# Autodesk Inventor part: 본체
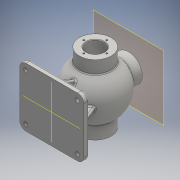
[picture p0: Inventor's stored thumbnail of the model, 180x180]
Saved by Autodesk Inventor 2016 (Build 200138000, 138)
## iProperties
Created: 2017-01
Part Number: 본체
Material: 일반
Document SubType Name: Modeling
Designer: Administrator
Density: 1 g/cm^3
Appearance: 기본값
Author: Administrator
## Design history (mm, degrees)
sketch "스케치1"
  geometry: L1 (0, 0)-(125, 0); L2 (125, 0)-(125, -115); L3 (125, -115)-(0, -115); L4 (0, -115)-(0, 0)
  constraints: 8 end point, 2 parallel, 1 horizontal, 1 perpendicular
  dimensions: "d0" = 115 distance of L1.end L2.end; "d1" = 125 distance of L2.end L3.end
extrude "돌출1" new body sketch "스케치1" distance "d2" = 10; taper "d3" = 0 deg
sketch "스케치2"
  geometry: L1 (-125, 0)-(-125, 115) reference; L2 (-125, 0)-(0, 0) reference; 1 further point
  dimensions: "d4" = 12 distance from line of L1 point (-113, 12); "d5" = 12 distance from line of L2 point (-113, 12)
hole "구멍1" sketch "스케치2" at (-113, 12) diameter "d6" = 8; stored, may be unused: countersink angle "d10" = 90 deg, drill point angle "d12" = 118 deg; dims "d7" = 6, "d8" = 12, "d9" = 3, "d11" = 8
fillet "모깎기1" dims "d19" = 12
node "작업 평면1"
sketch "스케치3"
  geometry: L1 (113.5, 116)-(113.5, 102.5); L2 (113.5, 85)-(-22.5, 85); L3 (-22.5, 102.5)-(-22.5, 116); L4 (91, 0)-(0, 0) reference; L5 (-12, 10)-(-12, 0) reference; L6 (-22.5, 116)-(2.512, 116); L7 (88.488, 116)-(113.5, 116); L8 (-6.5, 102.5)-(6.222, 102.5); L9 (-6.5, 102.5)-(-22.5, 102.5); L10 (113.5, 102.5)-(97.5, 102.5); L11 (97.5, 102.5)-(97.5, 103.5); L12 (97.5, 103.5)-(95.75, 103.5); L13 (95.75, 103.5)-(95.75, 102.5); L14 (95.75, 102.5)-(84.778, 102.5); A1 r 53 centre (45.5, 85) between (88.488, 116) and (2.512, 116); A2 r 43 centre (45.5, 85) between (84.778, 102.5) and (6.222, 102.5); 2 further points
  constraints: 24 end point, 7 perpendicular, 4 point on circle, 3 parallel, 2 centre point, 2 horizontal, 2 point on line, 1 midpoint, 1 vertical
  dimensions: "d22" = 136 distance of L3.end L1.start; "d23" = 85 distance between parallel lines of L4 L2; "d24" = 31 distance of L2.end L3.end; "d25" = 10.5 distance between parallel lines of L5 L3; "d26" = 53 radius of A1; "d28" = 43 radius of A2; "d36" = 17.5 distance between parallel lines of L2 L8; "d39" = 16 distance of L1.end L10.end; "d40" = 18.5 distance between parallel lines of L2 L12; "d41" = 17.5 distance between parallel lines of L2 L14; "d42" = 17.5 distance between parallel lines of L2 L10; "d43" = 1.75 distance of L11.end L12.end; "d44" = 136 distance between parallel lines of L3 L1; "d45" = 31 distance between parallel lines of L2 L6; "d46" = 68 distance of L2.end A1.centre
revolve "회전1" sketch "스케치3" stored, may be unused: angle "d32" = 90 deg
fillet "모깎기2" dims "d47" = 3
chamfer "모따기1" distance "d48" = 1; stored, may be unused: second distance "d49" = 2, angle "d50" = 45 deg
node "작업 평면2"
sketch "스케치4"
  geometry: L1 (-93.5, -125.5)-(-31.5, -125.5) reference; L2 (-125, -103)-(-125, -12) reference; C1 r 27 at (-62.5, -57.5); 1 further point
  constraints: 1 centre point
  dimensions: "d52" = 68 distance from line of C1.centre L1; "d53" = 62.5 distance from line of L2 C1.centre; "d54" = 54 diameter of C1
extrude "돌출2" join sketch "스케치4" stored distance "d55" = 10; taper "d56" = 0 deg
sketch "스케치5"
  geometry: C1 r 13 at (0, 0); 1 further point
  constraints: 1 centre point
  dimensions: "d57" = 26 diameter of C1
extrude "돌출3" cut sketch "스케치5" distance "d58" = 58; taper "d59" = 0 deg
fillet "모깎기3" dims "d60" = 3
chamfer "모따기2" distance "d61" = 1; stored, may be unused: second distance "d62" = 2, angle "d63" = 45 deg
sketch "스케치6" dims "d64" = 40
  geometry: 3 further points
  constraints: 1 horizontal alignment, 2 other
hole "구멍2" sketch "스케치6" at (-20, 0) diameter "d65" = 3.242; stored, may be unused: countersink angle "d69" = 90 deg, drill point angle "d71" = 118 deg; dims "d66" = 9, "d67" = 12, "d68" = 3, "d70" = 11
sketch "스케치7" dims "d75" = 48
  geometry: 3 further points
  constraints: 1 vertical alignment, 2 other
hole "구멍3" sketch "스케치7" at (0, 24) diameter "d76" = 3.242; stored, may be unused: countersink angle "d80" = 90 deg, drill point angle "d82" = 118 deg; dims "d77" = 16, "d78" = 12, "d79" = 3, "d81" = 19
sketch "스케치8" dims "d86" = 45
  geometry: 3 further points
  constraints: 1 vertical alignment, 2 other
hole "구멍4" sketch "스케치8" at (0, 22.5) diameter "d87" = 3.242; stored, may be unused: countersink angle "d91" = 90 deg, drill point angle "d93" = 118 deg; dims "d88" = 12, "d89" = 12, "d90" = 3, "d92" = 15
node "작업 평면3"
sketch "스케치11"
  geometry: L1 (101, 10)-(110, 10) reference; L2 (103, 10)-(86.485, 50.876); L3 (103, 10)-(-2, 10); L4 (101, 10)-(0, 10) reference; L5 (14.515, 50.876)-(-2, 10); L6 (-9, 10)-(0, 10) reference; L7 (113, 0)-(113, 7) reference; L8 (-12, 7)-(-12, 0) reference; A1 r 49.592 centre (50.5, 85) between (14.515, 50.876) and (86.485, 50.876)
  constraints: 6 end point, 2 point on circle, 2 point on line, 1 centre point
  dimensions: "d114" = 112 deg angle of L1 L2; "d115" = 112 deg angle of L6 L5; "d116" = 10 distance from line of L7 L2.start; "d117" = 10 distance from line of L8 L3.end
extrude "돌출5" join sketch "스케치11" stored distance "d118" = 8; taper "d119" = 0 deg
sketch "스케치12"
  geometry: L1 (79.219, 44.109)-(93, 10); L2 (91, 10)-(100, 10) reference; L3 (103, 7)-(103, 0) reference; A1 r 53 centre (45.5, 85) between (87.613, 117.179) and (87.613, 52.821) reference; 1 further point
  constraints: 2 end point, 1 point on circle
  dimensions: "d120" = 112 deg angle of L2 L1; "d121" = 0 distance from line of L2 L1.end; "d122" = 10 distance from line of L3 L1.end
feature "리브2" sketch "스케치12" dims "d123" = 1, "d124" = 8, "d125" = 0, "d126" = 0, "d127" = 1, "d128" = 1
fillet "모깎기4" dims "d129" = 3
fillet "모깎기5" dims "d130" = 3
node "솔리드1"
pattern_linear "직사각형 패턴1" dims "d15" = 101, "d18" = 91
pattern_circular "원형 패턴1" dims angle "d73" = 360 deg
pattern_circular "원형 패턴2" dims angle "d84" = 360 deg
pattern_circular "원형 패턴3" dims angle "d95" = 360 deg
mirror "대칭1"
other parameters: "d20" = -62.5, "d21" = 106, "d97" = -57.5
